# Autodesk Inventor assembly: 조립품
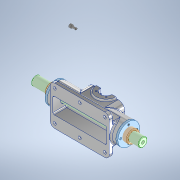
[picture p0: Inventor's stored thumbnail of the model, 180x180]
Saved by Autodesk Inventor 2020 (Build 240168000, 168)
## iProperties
Created: 2024-06
Part Number: 조립품
Document SubType Name: Assembly
Designer: oem
Author: oem
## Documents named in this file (6)
- C:\Users\oem\Desktop\740604V1017\조립품.iam
- C:\Users\oem\Desktop\740604V1017\본체.ipt
- C:\Users\oem\Desktop\740604V1017\랙.ipt
- C:\Users\oem\Desktop\740604V1017\오일레스 부시.ipt
- C:\Users\oem\Desktop\740604V1017\부시 커버.ipt
- C:\Users\oem\Desktop\740604V1017\육각 소켓 머리 볼트 M4x10.ipt
